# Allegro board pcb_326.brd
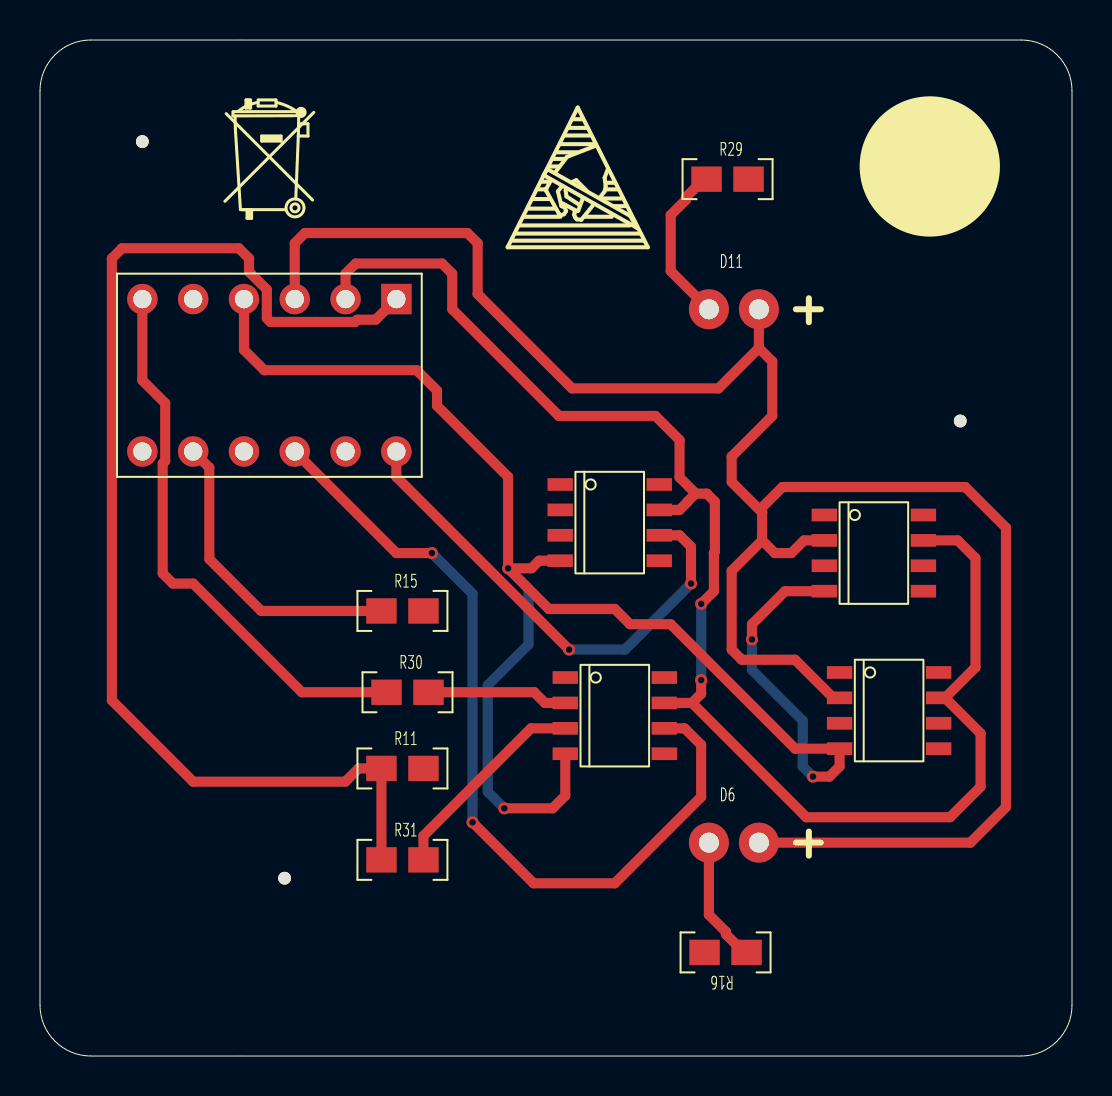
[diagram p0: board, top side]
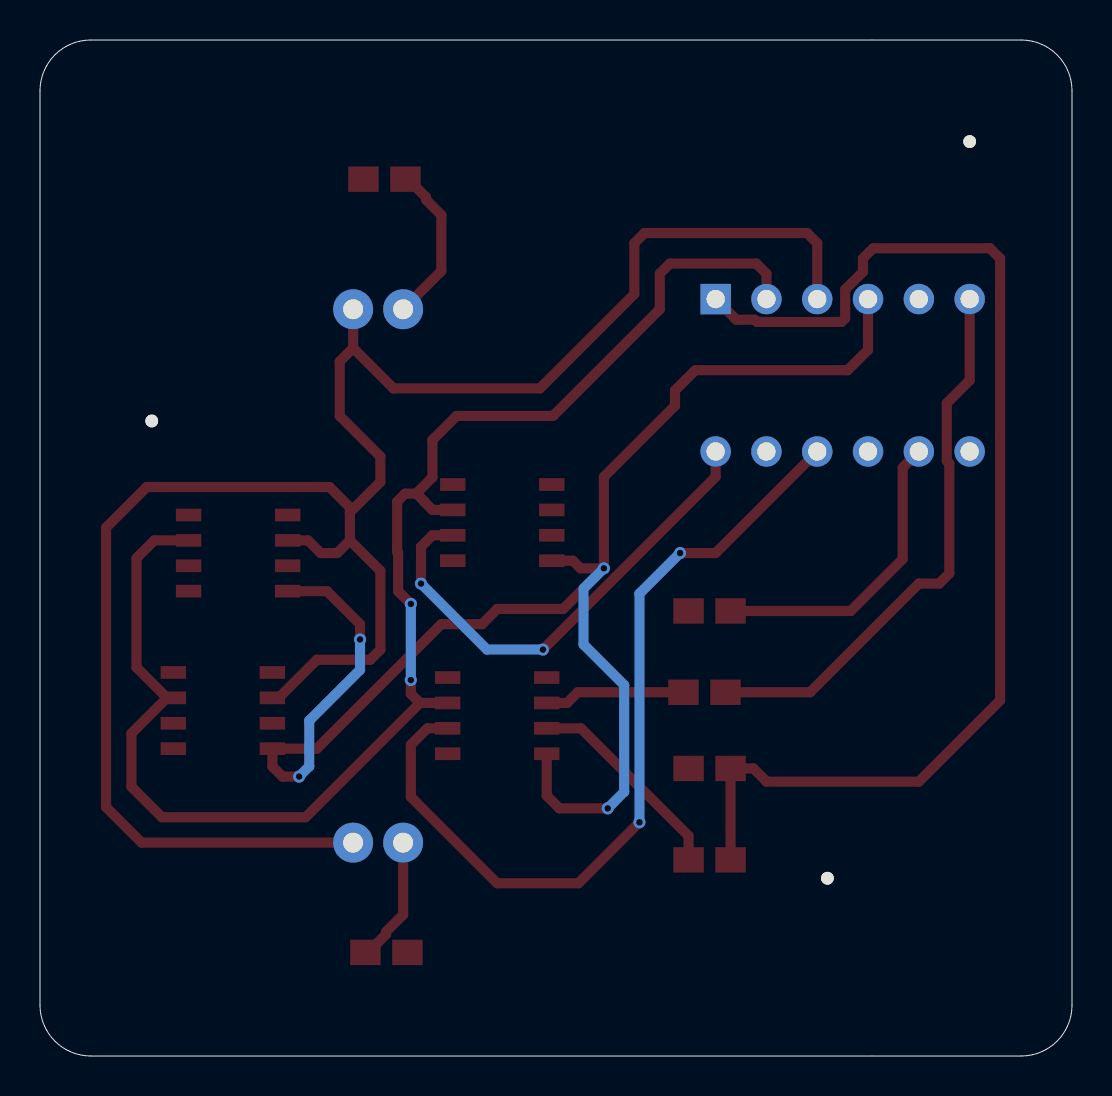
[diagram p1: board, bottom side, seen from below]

Outline 51.6 x 50.8 mm; copper layers: TOP, BOTTOM. Coordinates in mm from the lower left corner of the outline.
Outline path: 0,48.26 arc(0.74,50.06) 2.54,50.8 49.06,50.8 arc(50.86,50.06) 51.6,48.26 51.6,2.54 arc(50.86,0.74) 49.06,0 2.54,0 arc(0.74,0.74) 0,2.54 0,48.26

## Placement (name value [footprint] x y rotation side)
D6  LY_3336-TYP  [FG]  35.34 10.67 0 top
D11  LH_3344-TYP  [FG]  35.34 37.34 0 top
J1  HEADER 6X2  [DIP20_6]  11.47 34.04 270 top
NOREF  -  []  14.01 44.96 0 top
NOREF#2  -  [unnamed#2]  12.23 8.89 0 top
NOREF#3  -  [unnamed#2]  5.12 45.72 0 top
NOREF#4  -  []  45 44.7 0 top
NOREF#5  -  [unnamed#2]  46.01 31.75 0 top
NOREF#6  -  []  26.2 43.43 0 top
R11  10k  [0805]  18.07 14.48 0 top
R15  10k  [0805]  18.07 22.35 0 top
R16  270  [0805]  34.33 5.08 180 top
R29  270  [0805]  34.33 43.94 0 top
R30  10k  [0805]  18.33 18.29 0 top
R31  10k  [0805]  18.07 9.91 0 top
U5  LM741_1  [SOIC8]  28.49 26.67 0 top
U7  LM741_1  [SOIC8]  42.46 17.27 0 top
U13  LM741_1  [SOIC8]  28.74 17.02 0 top
U14  LM741_1  [SOIC8]  41.69 25.15 0 top

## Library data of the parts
D6 = LY_3336-TYP
D11 = LH_3344-TYP
J1 = HEADER 6X2
R11 R15 R16 R29-R31 = R
U5 U7 U13 U14 = LM741_1: Tolerance: ***; User Part Number: ***

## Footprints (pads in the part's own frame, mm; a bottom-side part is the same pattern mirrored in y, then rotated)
0805
  rect 1.524x1.27 smd: 1(-1,-0.1) 2(1.1,-0.1)
DIP20_6
  rect 1.524x1.524 hole 0.914: 1(-3.81,6.35)
  round 1.524 hole 0.914: 2(-3.81,3.81) 3(-3.81,1.27) 4(-3.81,-1.27) 5(-3.81,-3.81) 6(-3.81,-6.35) 7(3.81,-6.35) 8(3.81,-3.81) 9(3.81,-1.27) 10(3.81,1.27) 11(3.81,3.81) 12(3.81,6.35)
FG
  round 2 hole 1: 1(-1.9,0) 2(0.6,0)
SOIC8
  rect 1.27x0.635 smd: 1(-2.477,1.905) 2(-2.477,0.635) 3(-2.477,-0.635) 4(-2.477,-1.905) 5(2.477,-1.905) 6(2.477,-0.635) 7(2.477,0.635) 8(2.477,1.905)
unnamed#2
  round 0.635 hole 3.175 unplated: (0,0)

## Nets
VCC1+: J1.2 U5.7(V+) U7.7(V+) U13.7(V+) U14.7(V+)
VCC1-: J1.4 U5.4(V-) U7.4(V-) U13.4(V-) U14.4(V-)
0: D6.2 D11.2 J1.3 U7.2(IN+) U14.2(IN+)
VO0: J1.1 R11.1 R31.1
VO5: J1.10 U13.6(OUT)
VO6: J1.12 U5.6(OUT)
VO_0.8V: J1.8 R15.1
VO_3.5V: J1.6 R30.1
N181932: R29.2
N181986: R30.2 U13.2(IN+)
N181992: R31.2 U13.3(IN-)
N182997: R16.2
N183015: R15.2
N183115: R11.2
N184634: D11.1 R29.1
N1830530: D6.1 R16.1

Pads without a net: J1 5 7 9 11; U5 1 2 3 5 8; U7 1 3 5 6 8; U13 1 5 8; U14 1 3 5 6 8

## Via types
v1: diameter 0.61, hole 0.33, TOP to BOTTOM, 10 vias

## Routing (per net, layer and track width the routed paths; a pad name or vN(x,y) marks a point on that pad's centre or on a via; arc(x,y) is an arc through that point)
VCC1+: length 74.6
  TOP w0.508: J1.2 15.28,39.12 15.79,39.62 20.1,39.62 20.61,39.12 20.61,37.34 25.95,32 30.77,32 31.98,30.8 31.98,28.93 32.79,28.12 ; U14.7 45.89,25.78 46.77,24.89 46.77,19.43 45.25,17.91 ; 45.25,17.91 47.03,16.13 47.03,13.46 45.5,11.94 38.32,11.94 32.6,17.65 ; 45.25,17.91 U7.7 ; 32.6,17.65 33.06,18.11 v1(33.06,18.8) ; 32.6,17.65 U13.7 ; 32.79,28.12 32.77,28.12 32.37,27.72 32.37,27.7 31.98,27.3 U5.7 ; 32.79,28.12 33.34,28.12 33.74,27.72 33.74,25.21 33.69,25.15 33.69,23.24 v1(33.06,22.61)
  BOTTOM w0.508: v1(33.06,22.61) v1(33.06,18.8)
VCC1-: length 81.1
  TOP w0.508: v1(35.6,20.83) 35.6,21.59 37.25,23.24 U14.4 ; U5.4 24.95,24.76 24.57,24.38 v1(23.41,24.38) ; v1(23.41,24.38) 23.41,28.96 19.85,32.51 19.85,33.27 18.83,34.29 11.21,34.29 10.2,35.31 J1.4 ; v1(23.41,24.38) 25.44,22.35 28.74,22.35 29.5,21.59 31.53,21.59 37.76,15.37 U7.4 39.98,14.48 39.47,13.97 v1(38.65,13.97) ; 26.26,15.11 26.26,13.02 25.63,12.38 v1(23.22,12.38)
  BOTTOM w0.508: v1(23.22,12.38) 22.39,13.21 22.39,18.54 24.42,20.57 24.42,23.37 v1(23.41,24.38) ; v1(38.65,13.97) 38.14,14.48 38.14,16.76 35.6,19.3 v1(35.6,20.83)
0: length 102
  TOP w0.508: U14.2 38.2,25.78 37.57,25.15 36.74,25.15 36.11,25.78 ; J1.3 12.74,40.64 13.25,41.15 21.37,41.15 21.88,40.64 21.88,38.1 26.6,33.38 33.93,33.38 35.94,35.4 ; 36.11,25.78 36.11,27.18 ; 36.11,25.78 34.58,24.26 34.58,20.32 35.09,19.81 37.76,19.81 39.66,17.91 U7.2 ; 36.11,27.18 34.58,28.7 34.58,29.97 36.61,32 36.61,34.73 35.94,35.4 ; 36.11,27.18 36.11,27.43 37.12,28.45 46.27,28.45 48.3,26.42 48.3,12.45 46.52,10.67 D6.2 ; D11.2 35.94,35.4
VO0: length 59.8
  TOP w0.508: R31.1 R11.1 15.93,14.38 15.27,13.72 7.66,13.72 3.59,17.78 3.59,39.88 4.1,40.39 9.94,40.39 10.45,39.88 10.45,39.21 11.34,38.32 11.34,36.89 11.53,36.7 15.75,36.7 15.86,36.81 16.79,36.81 J1.1
VO5: length 42.5
  TOP w0.508: U13.6 32.23,16.38 33.06,15.56 33.06,12.95 28.74,8.64 24.68,8.64 v1(21.63,11.68) ; J1.10 17.82,25.15 v1(19.6,25.15)
  BOTTOM w0.508: v1(19.6,25.15) 21.63,23.11 v1(21.63,11.68)
VO6: length 24.6
  TOP w0.508: U5.6 31.98,26.04 32.55,25.46 v1(32.55,23.62) ; J1.12 17.82,28.96 v1(26.45,20.32)
  BOTTOM w0.508: v1(32.55,23.62) 29.25,20.32 v1(26.45,20.32)
VO_0.8V: length 15.4
  TOP w0.508: J1.8 8.47,29.42 8.47,24.85 11.06,22.25 R15.1
VO_3.5V: length 27.9
  TOP w0.508: J1.6 5.12,33.78 6.26,32.64 6.26,29.75 6.13,29.63 6.13,24.13 6.64,23.62 7.66,23.62 13.09,18.19 R30.1
N181986: length 7.1
  TOP w0.508: R30.2 24.71,18.19 25.25,17.65 U13.2
N181992: length 10.5
  TOP w0.508: U13.3 24.55,16.38 19.17,11.01 R31.2
N184634: length 8.1
  TOP w0.508: R29.1 33.2,43.84 32.3,42.94 32.3,42.81 31.53,42.05 31.53,39.25 D11.1
N1830530: length 6.3
  TOP w0.508: D6.1 33.44,7.06 34.3,6.21 34.3,6.08 35.2,5.18 R16.1
